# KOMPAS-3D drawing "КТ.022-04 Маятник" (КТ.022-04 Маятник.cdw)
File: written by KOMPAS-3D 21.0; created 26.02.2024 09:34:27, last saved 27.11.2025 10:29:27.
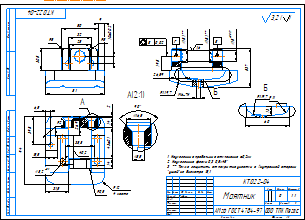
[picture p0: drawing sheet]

Sheet 1: A3, landscape

Document properties: Автор: User; Организация: Марсель; Полное имя файла: C:\Users\User\Desktop\Pelorus PRO доработки\Маятник\КТ.022-04 Маятник.cdw; Знак неуказанной шероховатости: 4; Параметр неуказанной шероховатости: 3,2

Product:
- Part/product: КТ.022-04 Маятник
    Комментарий: Марсель

Title block, sheet 1: Наименование: Маятник; designation: КТ.022-04; Материал: АМг6 ГОСТ 4784-97; Масса: 0; Количество листов документа: 1; organisation: ООО ТПК Пегас; Форматы листов документа: A3; stored path: D:\Marat\work\eholot\KazanTarget\детали\КТ.022-01 Полухомут маятниковый\Полухомут маятниковый _ КТ.022-01.cdw; Разработал: Гайсин

Views: Вид 1, Спереди, Проекционный вид 2, Местный разрез 1, Выносной элемент 6, Выносной элемент 7, Выносной элемент А, Выносной элемент, Выносной элемент Б
Referenced files in D:\Marat\work\eholot\KazanTarget\детали\КТ.022-01 Полухомут маятниковый\: КТ.022-01 Полухомут маятниковый.m3d
Referenced files in C:\Users\User\Desktop\Pelorus PRO доработки\Маятник\: КТ.022-04 Маятник.m3d
Referenced files in D:\Marat\work\eholot\KazanTarget\детали\КТ.022-03 Маятник\: КТ.022-03 Маятник.m3d
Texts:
  КТ.022-04 Маятник
Dimensions and other numbers on the sheet: 28; 50; 81; 32; 5; 10±0,02; 30,5; 9; 14; 94; 40,2; 26,9; 2; 43±0,1; 31,5; 38,8; 8,2; 12; 4 места; 0,5; 6,5; 39,8; 15,5; 8,5; 16,5; 13; 60; 11; 119,7; 0; 3,2; 1:1; 1

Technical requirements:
  Неуказанные предельные отклонения ±0,2мм.
  Неуказанные фаски 0,3..0,5х45°.
  ** Также защитить от покрытия участки с внутренней стороны
  "ушей" на диаметре 18,1.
